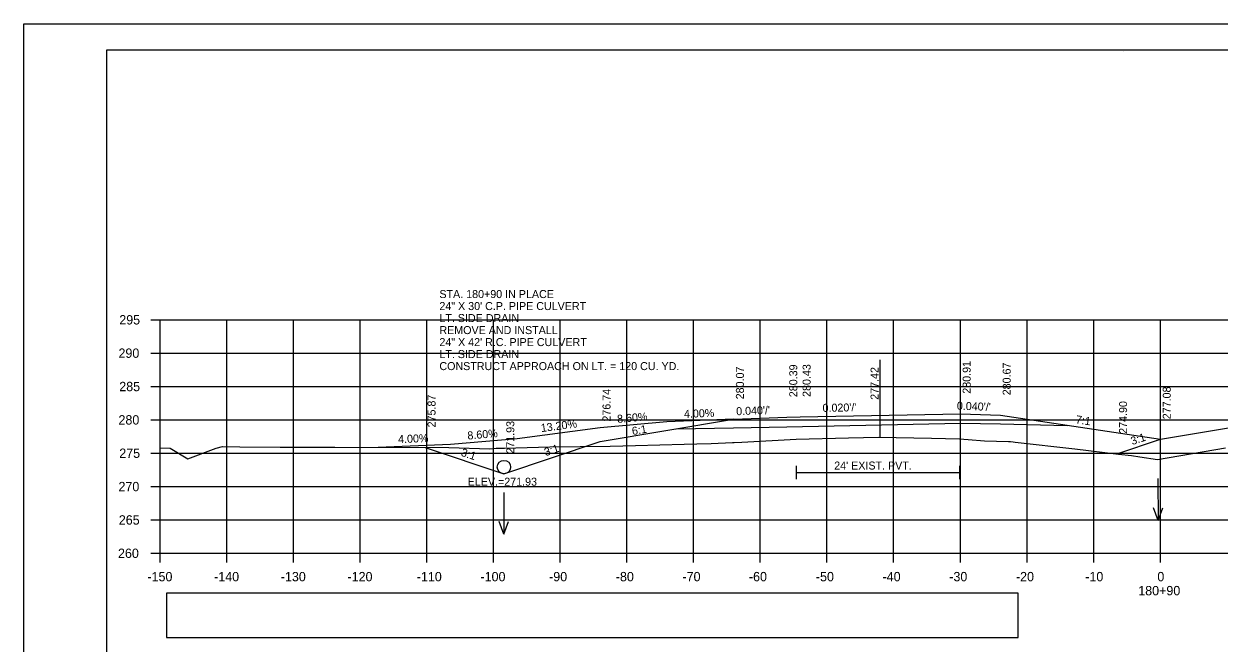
# Model space of a CAD drawing. Extents: x 285 to 4233, y -659 to 3710.
# Drawn here: x 1053.3 to 1232.5, y 2212.8 to 2305.6 of the extents above; entities that cross this region are included whole.
import ezdxf

# ---------------------------------------------------------------- set-up
doc = ezdxf.new("R2010")
doc.units = 0
for name, color, linetype in [('R_Alt Surface', 7, 'Continuous'), ('R_Axis', 7, 'Continuous'), ('R_Axis Annot', 7, 'Continuous'), ('R_Border', 7, 'Continuous'), ('R_Drive', 7, 'Continuous'), ('R_Exist Surface', 7, 'Continuous'), ('R_Fin Surface', 7, 'Continuous'), ('R_Grid', 7, 'Continuous'), ('R_No Plot', 7, 'Continuous'), ('R_Water', 7, 'Continuous'), ('R_Water Annot', 7, 'Continuous'), ('R_Xsect Elev', 7, 'Continuous'), ('R_Xsect Slope', 7, 'Continuous')]:
    doc.layers.add(name, color=color, linetype=linetype)

msp = doc.modelspace()

# ---------------------------------------------------------------- linework, layer by layer
at = {"layer": 'R_Alt Surface'}
for points in [[(1151.11, 2244.9), (1159.68, 2245.07), (1167.68, 2245.23), (1193.68, 2245.75), (1193.68, 2245.75), (1199.68, 2245.63), (1209.68, 2245.43)], [(1169.07, 2239.36), (1169.07, 2237.36)], [(1169.07, 2238.36), (1193.57, 2238.36)], [(1193.57, 2239.36), (1193.57, 2237.36)]]:
    msp.add_lwpolyline(points, dxfattribs=at)
at = {"layer": 'R_Axis'}
for p, q in [((1072.28, 2261.25), (1073.68, 2261.25)), ((1073.68, 2226.25), (1073.68, 2261.25)), ((1072.28, 2256.25), (1073.68, 2256.25)), ((1072.28, 2251.25), (1073.68, 2251.25)), ((1072.28, 2246.25), (1073.68, 2246.25)), ((1072.28, 2241.25), (1073.68, 2241.25)), ((1072.28, 2236.25), (1073.68, 2236.25)), ((1072.28, 2231.25), (1073.68, 2231.25)), ((1072.28, 2226.25), (1073.68, 2226.25)), ((1073.68, 2226.25), (1373.68, 2226.25)), ((1073.68, 2224.85), (1073.68, 2226.25)), ((1083.68, 2224.85), (1083.68, 2226.25)), ((1093.68, 2224.85), (1093.68, 2226.25)), ((1103.68, 2224.85), (1103.68, 2226.25)), ((1113.68, 2224.85), (1113.68, 2226.25)), ((1123.68, 2224.85), (1123.68, 2226.25)), ((1133.68, 2224.85), (1133.68, 2226.25)), ((1143.68, 2224.85), (1143.68, 2226.25)), ((1153.68, 2224.85), (1153.68, 2226.25)), ((1163.68, 2224.85), (1163.68, 2226.25)), ((1173.68, 2224.85), (1173.68, 2226.25)), ((1183.68, 2224.85), (1183.68, 2226.25)), ((1193.68, 2224.85), (1193.68, 2226.25)), ((1203.68, 2224.85), (1203.68, 2226.25)), ((1213.68, 2224.85), (1213.68, 2226.25)), ((1223.68, 2224.85), (1223.68, 2226.25))]:
    msp.add_line(p, q, dxfattribs=at)
at = {"layer": 'R_Axis Annot'}
msp.add_lwpolyline([(1074.67, 2213.6), (1202.36, 2213.6), (1202.36, 2220.25), (1074.67, 2220.25)], close=True, dxfattribs=at)
at = {"layer": 'R_Border'}
for p, q in [((1065.68, 2301.71), (1381.86, 2301.71)), ((1065.68, 2096.25), (1065.68, 2301.71)), ((1218.2, 2301.45), (1218.2, 2301.45)), ((1218.2, 2301.45), (1218.2, 2301.45))]:
    msp.add_line(p, q, dxfattribs=at)
at = {"layer": 'R_Drive'}
for p, q in [((1149.68, 2245.93), (1139.68, 2245.07)), ((1159.68, 2246.33), (1149.68, 2245.93)), ((1139.68, 2245.07), (1127.23, 2243.42)), ((1117.23, 2242.56), (1106.41, 2242.13)), ((1127.23, 2243.42), (1117.23, 2242.56))]:
    msp.add_line(p, q, dxfattribs=at)
at = {"layer": 'R_Exist Surface'}
msp.add_lwpolyline([(1073.68, 2242.07), (1075.21, 2242), (1077.85, 2240.4), (1082.1, 2241.99), (1083.04, 2242.25), (1085.66, 2242.23), (1091.7, 2242.17), (1096.19, 2242.16), (1099.89, 2242.14), (1116.98, 2242.11), (1123.11, 2241.9), (1124.1, 2242.01), (1125.34, 2242.03), (1132.14, 2242.23), (1141.18, 2242.31), (1144.96, 2242.39), (1152.26, 2242.62), (1154.19, 2242.66), (1156.34, 2242.7), (1159.51, 2242.84), (1159.75, 2242.85), (1160.94, 2242.92), (1169.07, 2243.36), (1176.92, 2243.56), (1181.39, 2243.68), (1189.35, 2243.5), (1193.57, 2243.41), (1194.83, 2243.31), (1197.31, 2243.09), (1200.91, 2243.02), (1201.2, 2243.01), (1201.59, 2242.96), (1201.92, 2242.93), (1210.83, 2241.93), (1217.4, 2241.12), (1219.34, 2240.9), (1220.61, 2240.69), (1223.23, 2240.31), (1233.46, 2242.08)], dxfattribs=at)
at = {"layer": 'R_Fin Surface'}
for points in [[(1217.13, 2241.16), (1223.68, 2243.34), (1247.68, 2247.34), (1253.68, 2247.58), (1277.68, 2247.1), (1279.68, 2247.06), (1287.68, 2246.74), (1307.68, 2243.4), (1317.24, 2240.22), (1323.38, 2242.27)], [(1113.44, 2242.12), (1125.25, 2238.18), (1139.68, 2242.99), (1159.68, 2246.33), (1167.68, 2246.65), (1169.68, 2246.69), (1193.68, 2247.17), (1199.68, 2246.93), (1223.68, 2243.34)]]:
    msp.add_lwpolyline(points, dxfattribs=at)
at = {"layer": 'R_Grid'}
for p, q in [((1073.68, 2261.25), (1373.68, 2261.25)), ((1073.68, 2226.25), (1073.68, 2261.25)), ((1083.68, 2226.25), (1083.68, 2261.25)), ((1093.68, 2226.25), (1093.68, 2261.25)), ((1103.68, 2226.25), (1103.68, 2261.25)), ((1113.68, 2226.25), (1113.68, 2261.25)), ((1123.68, 2226.25), (1123.68, 2261.25)), ((1133.68, 2226.25), (1133.68, 2261.25)), ((1143.68, 2226.25), (1143.68, 2261.25)), ((1153.68, 2226.25), (1153.68, 2261.25)), ((1163.68, 2226.25), (1163.68, 2261.25)), ((1173.68, 2226.25), (1173.68, 2261.25)), ((1183.68, 2226.25), (1183.68, 2261.25)), ((1193.68, 2226.25), (1193.68, 2261.25)), ((1203.68, 2226.25), (1203.68, 2261.25)), ((1213.68, 2226.25), (1213.68, 2261.25)), ((1223.68, 2226.25), (1223.68, 2261.25)), ((1073.68, 2256.25), (1373.68, 2256.25)), ((1073.68, 2251.25), (1373.68, 2251.25)), ((1073.68, 2246.25), (1373.68, 2246.25)), ((1073.68, 2241.25), (1373.68, 2241.25)), ((1073.68, 2236.25), (1373.68, 2236.25)), ((1073.68, 2231.25), (1373.68, 2231.25)), ((1073.68, 2226.25), (1373.68, 2226.25))]:
    msp.add_line(p, q, dxfattribs=at)
at = {"layer": 'R_No Plot'}
msp.add_line((1053.28, 2305.61), (1386.61, 2305.61), dxfattribs=at)
for points in [[(1053.27, 2305.61), (1386.61, 2305.61), (1386.61, 2092.27), (1053.27, 2092.27)], [(1299.6, 2301.71), (1319.22, 2301.71), (1319.22, 2291.83), (1335.33, 2291.83), (1358.53, 2291.83), (1358.65, 2263.68), (1381.86, 2263.68), (1381.86, 2096.25), (1065.68, 2096.25), (1065.68, 2301.71)]]:
    msp.add_lwpolyline(points, close=True, dxfattribs=at)
at = {"layer": 'R_Water'}
msp.add_circle((1125.25, 2239.18), 1, dxfattribs=at)
at = {"layer": 'R_Water Annot'}
for p, q in [((1223.31, 2237.44), (1223.34, 2231.15)), ((1125.22, 2235.37), (1125.24, 2229.09)), ((1223.34, 2231.15), (1222.63, 2233.07)), ((1223.34, 2231.15), (1224.03, 2233.08)), ((1125.24, 2229.09), (1124.54, 2231.01)), ((1125.24, 2229.09), (1125.94, 2231.01))]:
    msp.add_line(p, q, dxfattribs=at)
at = {"layer": 'R_Xsect Elev'}
msp.add_line((1181.68, 2243.67), (1181.68, 2255.24), dxfattribs=at)

# ---------------------------------------------------------------- texts
at = {"layer": 'R_Axis Annot'}
for s, p in [('295', (1067.57, 2260.55)), ('290', (1067.45, 2255.55)), ('285', (1067.57, 2250.55)), ('280', (1067.45, 2245.55)), ('275', (1067.57, 2240.55)), ('270', (1067.45, 2235.55)), ('265', (1067.5, 2230.55)), ('260', (1067.38, 2225.55)), ('-150', (1071.79, 2222.05)), ('-140', (1081.79, 2222.05)), ('-130', (1091.79, 2222.05)), ('-120', (1101.79, 2222.05)), ('-110', (1112.18, 2222.05)), ('-100', (1121.73, 2222.05)), ('-90', (1132.02, 2222.05)), ('-80', (1142.02, 2222.05)), ('-70', (1152.02, 2222.05)), ('-60', (1161.98, 2222.05)), ('-50', (1172.02, 2222.05)), ('-40', (1182.02, 2222.05)), ('-30', (1192.02, 2222.05)), ('-20', (1202.02, 2222.05)), ('-10', (1212.41, 2222.05)), ('0', (1223.22, 2222.05)), ('180+90', (1220.36, 2219.95))]:
    msp.add_text(s, height=1.4, dxfattribs=at).set_placement(p)
at = {"layer": 'R_Water'}
msp.add_text("24' EXIST. PVT.", height=1.2, dxfattribs=at).set_placement((1174.77, 2238.8))
at = {"layer": 'R_Water Annot'}
for s, p in [('STA. 180+90 IN PLACE', (1115.57, 2264.51)), ('24" X 30\' C.P. PIPE CULVERT', (1115.57, 2262.71)), ('LT. SIDE DRAIN', (1115.57, 2260.91)), ('REMOVE AND INSTALL', (1115.57, 2259.11)), ('24" X 42\' R.C. PIPE CULVERT', (1115.57, 2257.31)), ('LT. SIDE DRAIN', (1115.57, 2255.51)), ('CONSTRUCT APPROACH ON LT. = 120 CU. YD.', (1115.57, 2253.71))]:
    msp.add_text(s, height=1.2, dxfattribs=at).set_placement(p)
at = {"layer": 'R_Xsect Elev'}
for s, rotation, p in [('280.39', 90, (1169.23, 2249.65)), ('280.43', 90, (1171.23, 2249.69)), ('280.91', 90, (1195.23, 2250.17)), ('280.67', 90, (1201.23, 2249.93)), ('280.07', 90, (1161.23, 2249.33)), ('277.42', 90, (1181.42, 2249.26)), ('277.08', 90, (1225.23, 2246.34)), ('277.08', 90, (1225.23, 2246.34)), ('275.87', 90, (1114.99, 2245.12)), ('276.74', 90, (1141.23, 2245.99)), ('8.60%', 4.9153, (1142.27, 2245.79)), ('4.00%', 2.2906, (1152.26, 2246.53)), ('274.90', 90, (1218.68, 2244.16)), ('271.93', 90, (1126.8, 2241.18)), ('13.20%', 7.5196, (1130.86, 2244.41)), ('4.00%', 2.2906, (1109.4, 2242.75)), ('8.60%', 4.9153, (1119.82, 2243.29))]:
    msp.add_text(s, height=1.2, rotation=rotation, dxfattribs=at).set_placement(p)
msp.add_text('ELEV.=271.93', height=1.2, dxfattribs=at).set_placement((1119.81, 2236.38))
at = {"layer": 'R_Xsect Slope'}
for s, rotation, p in [("0.040'/'", 2.2907, (1160.09, 2246.94)), ("0.020'/'", 1.1458, (1173.03, 2247.44)), ("0.040'/'", 357.7095, (1193.14, 2247.79)), ('7:1', 351.4947, (1210.93, 2245.75)), ('6:1', 9.4614, (1144.54, 2243.96)), ('3:1', 18.4326, (1219.46, 2242.46)), ('3:1', 341.564, (1118.71, 2240.89)), ('3:1', 18.4337, (1131.51, 2240.8))]:
    msp.add_text(s, height=1.2, rotation=rotation, dxfattribs=at).set_placement(p)

doc.saveas('drawing.dxf')
